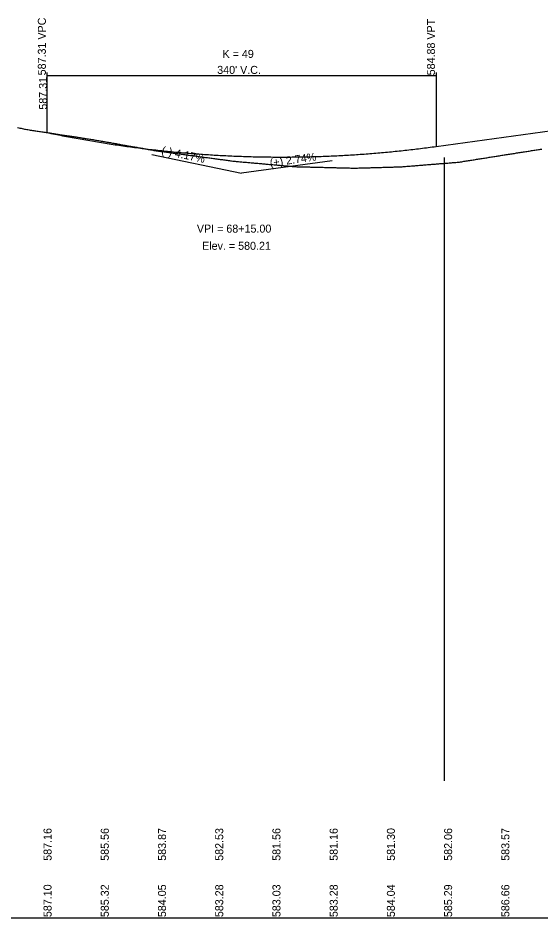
# Model space of a CAD drawing. Extents: x 1622419 to 1631737, y 887848 to 892020.
# Drawn here: x 1623117 to 1623574, y 890770 to 891557 of the extents above; entities that cross this region are included whole.
import ezdxf

# ---------------------------------------------------------------- set-up
doc = ezdxf.new("R2010")
doc.units = 0
for name, color, linetype in [('RD_DDB_GradeTX', 7, 'Continuous'), ('RD_DDB_Profile_EX', 7, 'Continuous'), ('RD_DDB_Profile_Lbl', 7, 'Continuous'), ('RD_DDB_Profile_PR', 7, 'Continuous'), ('RD_DDB_StripGrade', 7, 'Continuous'), ('RD_DDB_VCLbl', 7, 'Continuous'), ('RD_GPK_Profile_Cell', 7, 'Continuous'), ('RD_PD_Bridge', 7, 'Continuous')]:
    doc.layers.add(name, color=color, linetype=linetype)

msp = doc.modelspace()

# ---------------------------------------------------------------- linework, layer by layer
at = {"layer": 'RD_DDB_GradeTX'}
for p in [(1623233.71, 891437.43), (1623391.27, 891431.96)]:
    msp.add_line(p, (1623312.02, 891421.08), dxfattribs=at)
at = {"layer": 'RD_DDB_Profile_EX'}
for points in [[(1623116.38, 891460.94), (1623117.38, 891460.73), (1623118.38, 891460.51), (1623119.38, 891460.29), (1623120.38, 891460.07), (1623121.38, 891459.86), (1623122.38, 891459.64), (1623123.38, 891459.42), (1623124.38, 891459.24), (1623125.38, 891459.09), (1623126.38, 891458.93), (1623127.38, 891458.78), (1623128.38, 891458.63), (1623129.38, 891458.48), (1623130.38, 891458.33), (1623131.38, 891458.17), (1623132.38, 891458.02), (1623133.38, 891457.87), (1623134.38, 891457.72), (1623135.38, 891457.56), (1623136.38, 891457.41), (1623137.38, 891457.26), (1623138.38, 891457.11), (1623139.38, 891456.96), (1623140.38, 891456.8), (1623141.38, 891456.65), (1623142.38, 891456.5), (1623143.38, 891456.35), (1623144.38, 891456.2), (1623145.38, 891456.04), (1623146.38, 891455.89), (1623147.38, 891455.74), (1623148.38, 891455.59), (1623149.38, 891455.44), (1623150.38, 891455.28), (1623151.38, 891455.13), (1623152.38, 891454.98), (1623153.38, 891454.83), (1623154.38, 891454.68), (1623155.38, 891454.52), (1623156.38, 891454.37), (1623157.38, 891454.22), (1623158.38, 891454.07), (1623159.38, 891453.92), (1623160.38, 891453.76), (1623161.38, 891453.61), (1623162.38, 891453.46), (1623163.38, 891453.31), (1623164.38, 891453.15), (1623165.38, 891453), (1623166.38, 891452.85), (1623167.38, 891452.7), (1623168.38, 891452.55), (1623169.38, 891452.39), (1623170.38, 891452.24), (1623171.38, 891452.09), (1623172.38, 891451.94), (1623173.38, 891451.79), (1623174.38, 891451.63), (1623175.38, 891451.48), (1623176.38, 891451.33), (1623177.38, 891451.18), (1623178.38, 891451.02), (1623179.38, 891450.87), (1623180.38, 891450.72), (1623181.38, 891450.56), (1623182.38, 891450.39), (1623183.38, 891450.21), (1623184.38, 891450.04), (1623185.38, 891449.86), (1623186.38, 891449.68), (1623187.38, 891449.5)], [(1623187.38, 891449.5), (1623188.38, 891449.33), (1623189.38, 891449.15), (1623190.38, 891448.97), (1623191.38, 891448.8), (1623192.38, 891448.62), (1623193.38, 891448.44), (1623194.38, 891448.27), (1623195.38, 891448.09), (1623196.38, 891447.91), (1623197.38, 891447.73), (1623198.38, 891447.56), (1623199.38, 891447.38), (1623200.38, 891447.2), (1623201.38, 891447.03), (1623202.38, 891446.85), (1623203.38, 891446.67), (1623204.38, 891446.49), (1623205.38, 891446.32), (1623206.38, 891446.14), (1623207.38, 891445.96), (1623208.38, 891445.79), (1623209.38, 891445.61), (1623210.38, 891445.43), (1623211.38, 891445.25), (1623212.38, 891445.08), (1623213.38, 891444.9), (1623214.38, 891444.72), (1623215.38, 891444.55), (1623216.38, 891444.37), (1623217.38, 891444.19), (1623218.38, 891444.01), (1623219.38, 891443.84), (1623220.38, 891443.66), (1623221.38, 891443.48), (1623222.38, 891443.31), (1623223.38, 891443.13), (1623224.38, 891442.95), (1623225.38, 891442.77), (1623226.38, 891442.6), (1623227.38, 891442.42), (1623228.38, 891442.24), (1623229.38, 891442.07), (1623230.38, 891441.89), (1623231.38, 891441.71), (1623232.38, 891441.53), (1623233.38, 891441.36), (1623234.38, 891441.18), (1623235.38, 891441), (1623236.38, 891440.83), (1623237.38, 891440.68), (1623238.38, 891440.54), (1623239.38, 891440.41), (1623240.38, 891440.27), (1623241.38, 891440.14), (1623242.38, 891440), (1623243.38, 891439.87), (1623244.38, 891439.73), (1623245.38, 891439.6), (1623246.38, 891439.47), (1623247.38, 891439.33), (1623248.38, 891439.2), (1623249.38, 891439.06), (1623250.38, 891438.93), (1623251.38, 891438.79), (1623252.38, 891438.66), (1623253.38, 891438.52), (1623254.38, 891438.39), (1623255.38, 891438.25), (1623256.38, 891438.12), (1623257.38, 891437.99), (1623258.38, 891437.85), (1623259.38, 891437.72), (1623260.38, 891437.58), (1623261.38, 891437.45), (1623262.38, 891437.31), (1623263.38, 891437.18), (1623264.38, 891437.04), (1623265.38, 891436.91), (1623266.38, 891436.77), (1623267.38, 891436.64), (1623268.38, 891436.51), (1623269.38, 891436.37), (1623270.38, 891436.24), (1623271.38, 891436.1), (1623272.38, 891435.97), (1623273.38, 891435.83), (1623274.38, 891435.7), (1623275.38, 891435.56), (1623276.38, 891435.43), (1623277.38, 891435.3), (1623278.38, 891435.16), (1623279.38, 891435.03), (1623280.38, 891434.89), (1623281.38, 891434.76), (1623282.38, 891434.62), (1623283.38, 891434.49), (1623284.38, 891434.35), (1623285.38, 891434.22), (1623286.38, 891434.08), (1623287.38, 891433.95)], [(1623487.38, 891429.54), (1623488.38, 891429.62), (1623489.38, 891429.7), (1623490.38, 891429.78), (1623491.38, 891429.86), (1623492.38, 891429.94), (1623493.38, 891430.02), (1623494.38, 891430.1), (1623495.38, 891430.18), (1623496.38, 891430.26), (1623497.38, 891430.34), (1623498.38, 891430.42), (1623499.38, 891430.5), (1623500.38, 891430.58), (1623501.38, 891430.66), (1623502.38, 891430.77), (1623503.38, 891430.93), (1623504.38, 891431.09), (1623505.38, 891431.25), (1623506.38, 891431.41), (1623507.38, 891431.57), (1623508.38, 891431.73), (1623509.38, 891431.89), (1623510.38, 891432.05), (1623511.38, 891432.21), (1623512.38, 891432.37), (1623513.38, 891432.53), (1623514.38, 891432.69), (1623515.38, 891432.85), (1623516.38, 891433.01), (1623517.38, 891433.17), (1623518.38, 891433.32), (1623519.38, 891433.48), (1623520.38, 891433.64), (1623521.38, 891433.8), (1623522.38, 891433.96), (1623523.38, 891434.12), (1623524.38, 891434.28), (1623525.38, 891434.44), (1623526.38, 891434.59), (1623527.38, 891434.75), (1623528.38, 891434.91), (1623529.38, 891435.07), (1623530.38, 891435.23), (1623531.38, 891435.39), (1623532.38, 891435.54), (1623533.38, 891435.7), (1623534.38, 891435.86), (1623535.38, 891436.02), (1623536.38, 891436.18), (1623537.38, 891436.34), (1623538.38, 891436.49), (1623539.38, 891436.65), (1623540.38, 891436.81), (1623541.38, 891436.97), (1623542.38, 891437.12), (1623543.38, 891437.28), (1623544.38, 891437.44), (1623545.38, 891437.6), (1623546.38, 891437.75), (1623547.38, 891437.91), (1623548.38, 891438.07), (1623549.38, 891438.23), (1623550.38, 891438.38), (1623551.38, 891438.54), (1623552.38, 891438.7), (1623553.38, 891438.86), (1623554.38, 891439.01), (1623555.38, 891439.17), (1623556.38, 891439.33), (1623557.38, 891439.48), (1623558.38, 891439.64), (1623559.38, 891439.8), (1623560.38, 891439.95), (1623561.38, 891440.11), (1623562.38, 891440.27), (1623563.38, 891440.42), (1623564.38, 891440.58), (1623565.38, 891440.74), (1623566.38, 891440.89), (1623567.38, 891441.05), (1623568.38, 891441.2), (1623569.38, 891441.36), (1623570.38, 891441.52), (1623571.38, 891441.67), (1623572.38, 891441.83), (1623573.38, 891441.98), (1623574.38, 891442.14)], [(1623287.38, 891433.95), (1623288.38, 891433.82), (1623289.38, 891433.68), (1623290.38, 891433.55), (1623291.38, 891433.41), (1623292.38, 891433.28), (1623293.38, 891433.14), (1623294.38, 891433.01), (1623295.38, 891432.87), (1623296.38, 891432.74), (1623297.38, 891432.61), (1623298.38, 891432.47), (1623299.38, 891432.34), (1623300.38, 891432.2), (1623301.38, 891432.07), (1623302.38, 891431.93), (1623303.38, 891431.8), (1623304.38, 891431.66), (1623305.38, 891431.54), (1623306.38, 891431.44), (1623307.38, 891431.35), (1623308.38, 891431.26), (1623309.38, 891431.17), (1623310.38, 891431.08), (1623311.38, 891431), (1623312.38, 891430.91), (1623313.38, 891430.82), (1623314.38, 891430.73), (1623315.38, 891430.64), (1623316.38, 891430.55), (1623317.38, 891430.46), (1623318.38, 891430.38), (1623319.38, 891430.29), (1623320.38, 891430.2), (1623321.38, 891430.11), (1623322.38, 891430.02), (1623323.38, 891429.93), (1623324.38, 891429.85), (1623325.38, 891429.76), (1623326.38, 891429.67), (1623327.38, 891429.58), (1623328.38, 891429.49), (1623329.38, 891429.4), (1623330.38, 891429.31), (1623331.38, 891429.23), (1623332.38, 891429.14), (1623333.38, 891429.05), (1623334.38, 891428.96), (1623335.38, 891428.87), (1623336.38, 891428.77), (1623337.38, 891428.68), (1623338.38, 891428.59), (1623339.38, 891428.5), (1623340.38, 891428.41), (1623341.38, 891428.32), (1623342.38, 891428.23), (1623343.38, 891428.14), (1623344.38, 891428.05), (1623345.38, 891427.96), (1623346.38, 891427.87), (1623347.38, 891427.78), (1623348.38, 891427.69), (1623349.38, 891427.6), (1623350.38, 891427.51), (1623351.38, 891427.42), (1623352.38, 891427.33), (1623353.38, 891427.24), (1623354.38, 891427.15), (1623355.38, 891427.05), (1623356.38, 891426.96), (1623357.38, 891426.87), (1623358.38, 891426.79), (1623359.38, 891426.76), (1623360.38, 891426.74), (1623361.38, 891426.71), (1623362.38, 891426.69), (1623363.38, 891426.66), (1623364.38, 891426.64), (1623365.38, 891426.61), (1623366.38, 891426.59), (1623367.38, 891426.56), (1623368.38, 891426.54), (1623369.38, 891426.51), (1623370.38, 891426.49), (1623371.38, 891426.46), (1623372.38, 891426.44), (1623373.38, 891426.41), (1623374.38, 891426.39), (1623375.38, 891426.36), (1623376.38, 891426.34), (1623377.38, 891426.31), (1623378.38, 891426.29), (1623379.38, 891426.26), (1623380.38, 891426.23), (1623381.38, 891426.21), (1623382.38, 891426.18), (1623383.38, 891426.16), (1623384.38, 891426.13), (1623385.38, 891426.11), (1623386.38, 891426.08), (1623387.38, 891426.06)], [(1623387.38, 891426.06), (1623388.38, 891426.03), (1623389.38, 891426.01), (1623390.38, 891425.98), (1623391.38, 891425.96), (1623392.38, 891425.93), (1623393.38, 891425.91), (1623394.38, 891425.88), (1623395.38, 891425.86), (1623396.38, 891425.83), (1623397.38, 891425.81), (1623398.38, 891425.78), (1623399.38, 891425.76), (1623400.38, 891425.73), (1623401.38, 891425.71), (1623402.38, 891425.68), (1623403.38, 891425.66), (1623404.38, 891425.63), (1623405.38, 891425.61), (1623406.38, 891425.58), (1623407.38, 891425.55), (1623408.38, 891425.53), (1623409.38, 891425.5), (1623410.38, 891425.48), (1623411.38, 891425.49), (1623412.38, 891425.52), (1623413.38, 891425.55), (1623414.38, 891425.58), (1623415.38, 891425.6), (1623416.38, 891425.63), (1623417.38, 891425.66), (1623418.38, 891425.69), (1623419.38, 891425.72), (1623420.38, 891425.75), (1623421.38, 891425.77), (1623422.38, 891425.8), (1623423.38, 891425.83), (1623424.38, 891425.86), (1623425.38, 891425.89), (1623426.38, 891425.91), (1623427.38, 891425.94), (1623428.38, 891425.97), (1623429.38, 891426), (1623430.38, 891426.03), (1623431.38, 891426.05), (1623432.38, 891426.08), (1623433.38, 891426.11), (1623434.38, 891426.14), (1623435.38, 891426.17), (1623436.38, 891426.2), (1623437.38, 891426.22), (1623438.38, 891426.25), (1623439.38, 891426.28), (1623440.38, 891426.31), (1623441.38, 891426.34), (1623442.38, 891426.36), (1623443.38, 891426.39), (1623444.38, 891426.42), (1623445.38, 891426.45), (1623446.38, 891426.48), (1623447.38, 891426.5), (1623448.38, 891426.53), (1623449.38, 891426.56), (1623450.38, 891426.59), (1623451.38, 891426.65), (1623452.38, 891426.73), (1623453.38, 891426.8), (1623454.38, 891426.88), (1623455.38, 891426.96), (1623456.38, 891427.04), (1623457.38, 891427.12), (1623458.38, 891427.2), (1623459.38, 891427.28), (1623460.38, 891427.36), (1623461.38, 891427.44), (1623462.38, 891427.53), (1623463.38, 891427.61), (1623464.38, 891427.69), (1623465.38, 891427.77), (1623466.38, 891427.85), (1623467.38, 891427.93), (1623468.38, 891428.01), (1623469.38, 891428.09), (1623470.38, 891428.17), (1623471.38, 891428.25), (1623472.38, 891428.33), (1623473.38, 891428.41), (1623474.38, 891428.49), (1623475.38, 891428.57), (1623476.38, 891428.65), (1623477.38, 891428.73), (1623478.38, 891428.81), (1623479.38, 891428.89), (1623480.38, 891428.97), (1623481.38, 891429.05), (1623482.38, 891429.14), (1623483.38, 891429.22), (1623484.38, 891429.3), (1623485.38, 891429.38), (1623486.38, 891429.46), (1623487.38, 891429.54)]]:
    msp.add_lwpolyline(points, dxfattribs=at)
at = {"layer": 'RD_DDB_Profile_PR'}
msp.add_line((1623482.02, 891444.41), (1623592.02, 891459.51), dxfattribs=at)
msp.add_spline([(1623142.02, 891456.57), (1623148.82, 891455.17), (1623155.62, 891453.82), (1623162.42, 891452.52), (1623169.22, 891451.27), (1623176.02, 891450.06), (1623182.82, 891448.9), (1623189.62, 891447.78), (1623196.42, 891446.72), (1623203.22, 891445.7), (1623210.02, 891444.73), (1623216.82, 891443.8), (1623223.62, 891442.92), (1623230.42, 891442.09), (1623237.22, 891441.31), (1623244.02, 891440.57), (1623250.82, 891439.88), (1623257.62, 891439.24), (1623264.42, 891438.64), (1623271.22, 891438.09), (1623278.02, 891437.59), (1623284.82, 891437.13), (1623291.62, 891436.73), (1623298.42, 891436.37), (1623305.22, 891436.05), (1623312.02, 891435.79), (1623318.82, 891435.57), (1623325.62, 891435.39), (1623332.42, 891435.27), (1623339.22, 891435.19), (1623346.02, 891435.16), (1623352.82, 891435.17), (1623359.62, 891435.24), (1623366.42, 891435.35), (1623373.22, 891435.5), (1623380.02, 891435.71), (1623386.82, 891435.96), (1623393.62, 891436.26), (1623400.42, 891436.6), (1623407.22, 891436.99), (1623414.02, 891437.43), (1623420.82, 891437.92), (1623427.62, 891438.45), (1623434.42, 891439.03), (1623441.22, 891439.66), (1623448.02, 891440.34), (1623454.82, 891441.06), (1623461.62, 891441.83), (1623468.42, 891442.64), (1623475.22, 891443.5), (1623482.02, 891444.41)], degree=3, dxfattribs=at)
at = {"layer": 'RD_DDB_VCLbl'}
for p, q in [((1623142.02, 891509.07), (1623142.02, 891456.57)), ((1623142.02, 891506.57), (1623482.02, 891506.57)), ((1623482.02, 891509.07), (1623482.02, 891444.41))]:
    msp.add_line(p, q, dxfattribs=at)
at = {"layer": 'RD_GPK_Profile_Cell'}
msp.add_line((1622497.02, 890770.02), (1623797.02, 890770.02), dxfattribs=at)
at = {"layer": 'RD_PD_Bridge'}
msp.add_line((1623489.32, 890890.02), (1623489.32, 891434.69), dxfattribs=at)

# ---------------------------------------------------------------- texts
at = {"layer": 'RD_DDB_GradeTX'}
for s, rotation, p in [('(-) 4.17%', 348.20969, (1623241.63, 891437.82)), ('(+) 2.74%', 7.81488, (1623337.18, 891426.55))]:
    msp.add_text(s, height=7, rotation=rotation, dxfattribs=at).set_placement(p)
at = {"layer": 'RD_DDB_Profile_Lbl'}
msp.add_text('587.31', height=7, rotation=90, dxfattribs=at).set_placement((1623142.02, 891476.57))
for s, p in [('VPI = 68+15.00', (1623272.99, 891369.08)), ('Elev. = 580.21', (1623277.55, 891354.08))]:
    msp.add_text(s, height=7, dxfattribs=at).set_placement(p)
at = {"layer": 'RD_DDB_StripGrade'}
for s, p in [('587.31 VPC', (1623141.02, 891506.57)), ('584.88 VPT', (1623481.02, 891506.57)), ('587.16', (1623146.02, 890820.02)), ('585.56', (1623196.02, 890820.02)), ('583.87', (1623246.02, 890820.02)), ('582.53', (1623296.02, 890820.02)), ('581.56', (1623346.02, 890820.02)), ('581.16', (1623396.02, 890820.02)), ('581.30', (1623446.02, 890820.02)), ('582.06', (1623496.02, 890820.02)), ('583.57', (1623546.02, 890820.02)), ('587.10', (1623146.02, 890770.77)), ('585.32', (1623196.02, 890770.77)), ('584.05', (1623246.02, 890770.77)), ('583.28', (1623296.02, 890770.77)), ('583.03', (1623346.02, 890770.77)), ('583.28', (1623396.02, 890770.77)), ('584.04', (1623446.02, 890770.77)), ('585.29', (1623496.02, 890770.77)), ('586.66', (1623546.02, 890770.77))]:
    msp.add_text(s, height=7, rotation=90, dxfattribs=at).set_placement(p)
at = {"layer": 'RD_DDB_VCLbl'}
for s, p in [('K = 49', (1623295.4, 891521.82)), ("340' V.C.", (1623290.76, 891507.82))]:
    msp.add_text(s, height=7, dxfattribs=at).set_placement(p)

doc.saveas('drawing.dxf')
